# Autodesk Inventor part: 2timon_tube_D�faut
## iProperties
Created: 2011-01
Part Number: 2timon_tube_D�faut
Document SubType Name: Modeling
Designer: eric
Density: 1 g/cm^3
Mass: 59.322 g
Surface Area: 1189.44 cm^2
Volume: 59.322 cm^3
Author: eric
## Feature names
1. Base1
